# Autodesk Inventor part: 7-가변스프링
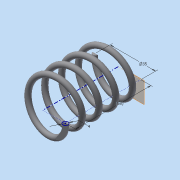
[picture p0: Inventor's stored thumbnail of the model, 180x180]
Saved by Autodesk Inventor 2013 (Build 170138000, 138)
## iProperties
Created: 2015-03
Part Number: 7-가변스프링
Material: 강철, 탄소
Document SubType Name: Modeling
Designer: Administrator
Density: 7.87 g/cm^3
Mass: 48.2733 g
Surface Area: 62.0009 cm^2
Volume: 6.13384 cm^3
Author: Administrator
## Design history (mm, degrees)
sketch "스케치1"
  geometry: L1 (0, 0)-(17.5, 0); L2 (17.5, 0)-(17.5, 43.5); L3 (17.5, 43.5)-(0, 43.5); L4 (0, 43.5)-(0, 0); C1 r 2 at (17.5, 0)
  constraints: 8 end point, 2 parallel, 1 centre point, 1 coincident, 1 horizontal, 1 perpendicular, 1 point on line
  dimensions: "d0" = 43.5 distance of L1.end L2.end (derived); "d2" = 35 diameter of L2 L4; "d3" = 4 diameter of C1
feature "코일1" sketch "스케치1" pitch "d4" = 10; turns "d6" = 4.5; dims "d5" = 43.5 (= d0), "d7" = 0, angle "d8" = 90 deg, angle "d9" = 90 deg, "d10" = 0, "d11" = 0
sketch "스케치2"
  geometry: L1 (-19.5, 0)-(-15.5, 0) reference; 1 further point
  constraints: 1 horizontal alignment
extrude "돌출1" cut sketch "스케치2" stored distance "d12" = 10; taper "d13" = 0 deg
node "작업 평면1"
sketch "스케치3"
  geometry: L1 (-19.5, 0)-(-15.5, 0) reference; 1 further point
  constraints: 1 horizontal alignment
extrude "돌출2" cut sketch "스케치3" stored distance "d15" = 10; taper "d16" = 0 deg
node "솔리드1"
node "절단 모서리 투영1"
node "절단 모서리 투영2"
other parameters: "d14" = -43.5 (= -d0)
